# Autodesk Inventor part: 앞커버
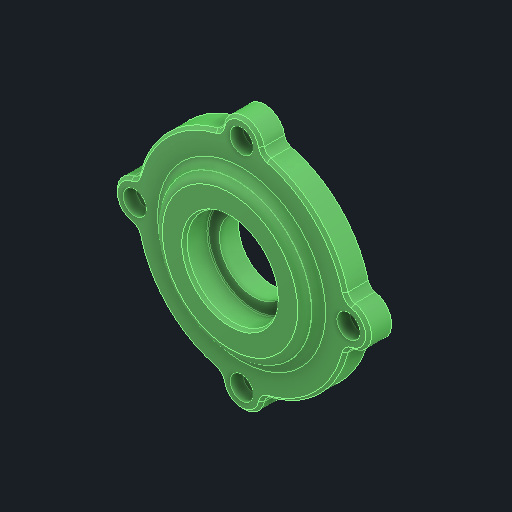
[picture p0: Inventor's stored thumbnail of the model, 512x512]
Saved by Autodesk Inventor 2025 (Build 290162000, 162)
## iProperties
Created: 2025-08
Part Number: 앞커버
Material: 알루미늄 6061
Document SubType Name: Modeling
Designer: infra005
Density: 2.71 g/cm^3
Appearance: 기본값
Company: 한국ATC센터
Author: jhkim
Sending System: Autodesk Inventor 2026
Preprocessor: ST-DEVELOPER v20.1
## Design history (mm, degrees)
feature "솔리드1"
node "솔리드2"
